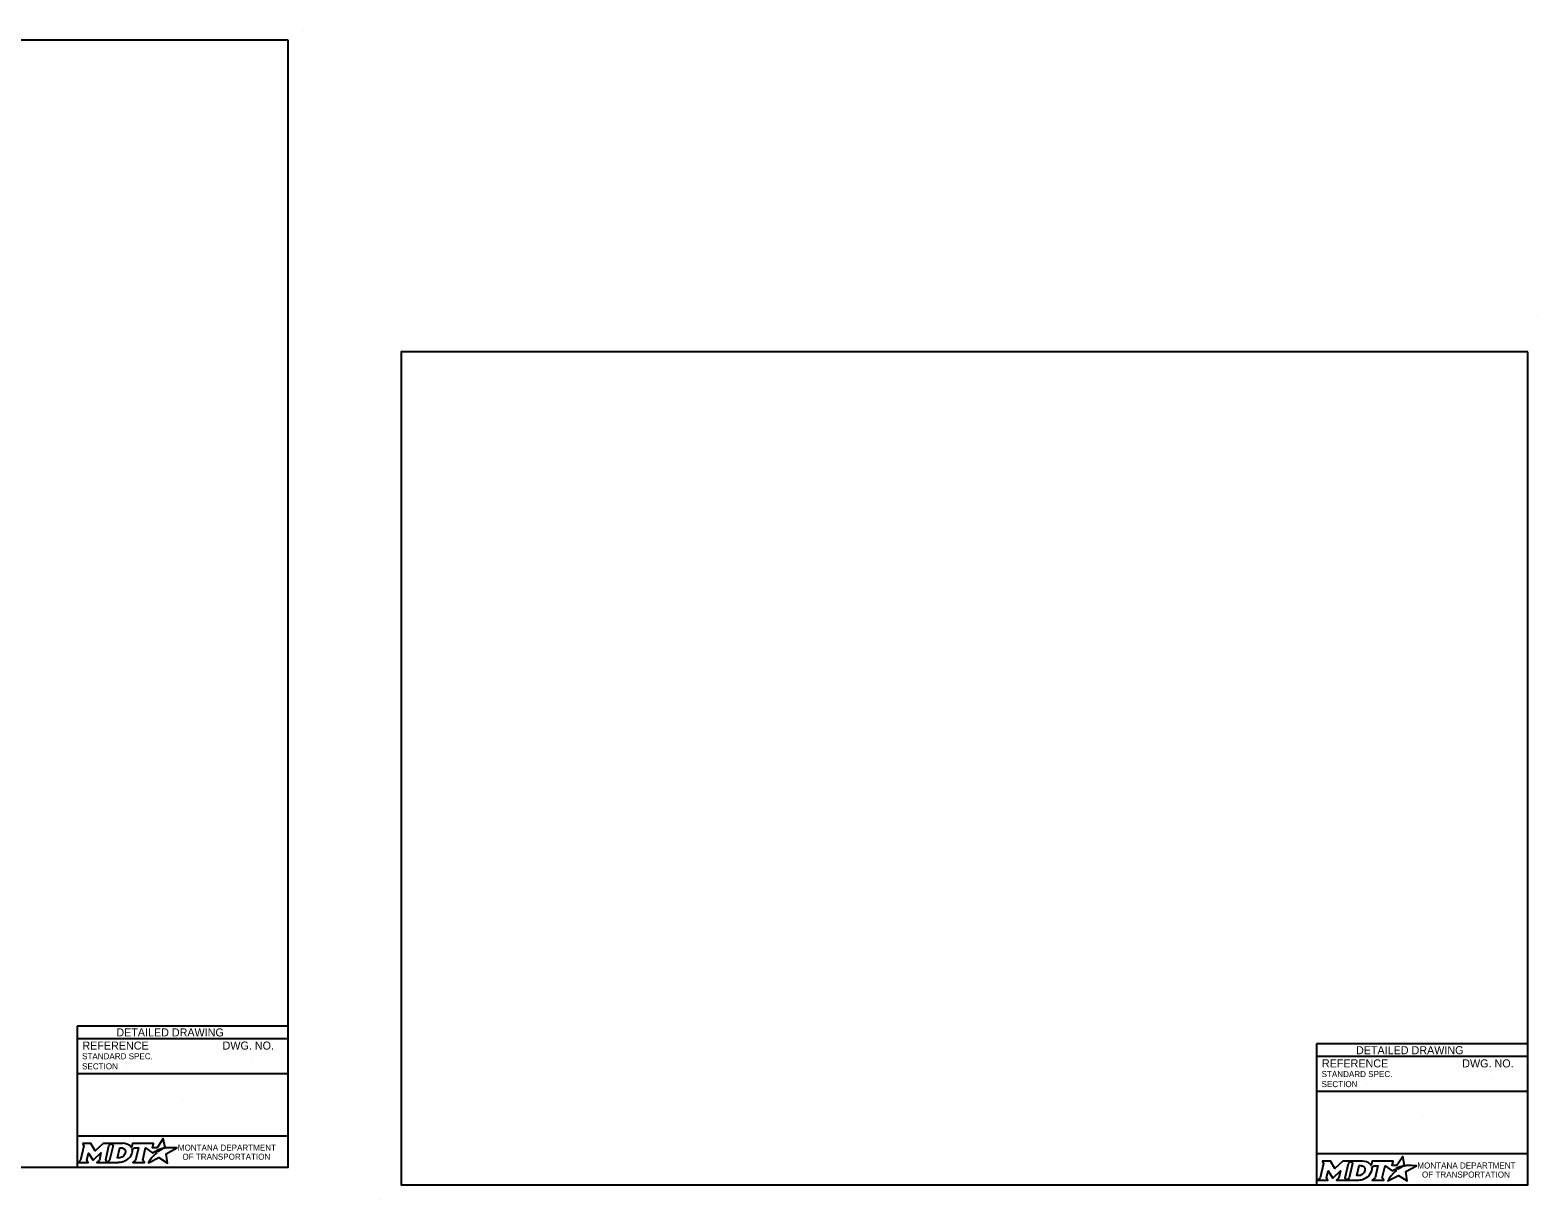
# Model space of a CAD drawing. Extents: x 49991.4 to 50021, y 49987.6 to 50011.4.
# Drawn here: x 50006.05 to 50021.04, y 49999.74 to 50011.36 of the extents above; entities that cross this region are included whole.
import ezdxf

# ---------------------------------------------------------------- set-up
doc = ezdxf.new("R2010")
doc.units = 0
for name, color, linetype in [('Default', 7, 'Continuous'), ('Level 1', 7, 'Continuous'), ('Level 2', 7, 'Continuous'), ('Level 4', 7, 'Continuous')]:
    doc.layers.add(name, color=color, linetype=linetype)

msp = doc.modelspace()

# ---------------------------------------------------------------- linework, layer by layer
at = {"layer": 'Default'}
for points in [[(50018.893, 50000.121), (50018.907, 50000.097), (50018.874, 49999.954), (50018.848, 49999.931), (50018.95, 49999.931), (50018.936, 49999.954), (50018.952, 50000.024), (50018.996, 49999.955), (50019.002, 49999.955), (50019.077, 50000.025), (50019.06, 49999.954), (50019.035, 49999.932), (50019.137, 49999.932), (50019.123, 49999.955), (50019.156, 50000.097)], [(50019.156, 50000.097), (50019.182, 50000.121), (50019.099, 50000.121), (50019.02, 50000.048), (50018.975, 50000.12), (50018.893, 50000.121)], [(50019.295, 50000.121), (50019.182, 50000.121), (50019.196, 50000.098), (50019.163, 49999.954), (50019.137, 49999.932), (50019.248, 49999.932)], [(50019.319, 50000.034), (50019.318, 50000.026), (50019.315, 50000.017), (50019.311, 50000.008), (50019.305, 50000.001), (50019.299, 49999.994), (50019.291, 49999.988), (50019.282, 49999.983), (50019.273, 49999.979), (50019.264, 49999.977), (50019.255, 49999.976), (50019.239, 49999.976), (50019.263, 50000.076), (50019.279, 50000.076), (50019.286, 50000.075), (50019.294, 50000.073), (50019.301, 50000.07), (50019.307, 50000.066), (50019.311, 50000.061), (50019.315, 50000.055), (50019.318, 50000.049), (50019.319, 50000.042), (50019.32, 50000.038), (50019.319, 50000.034)], [(50019.7, 50000.068), (50019.69, 50000.074), (50019.702, 50000.076), (50019.713, 50000.078), (50019.696, 50000.168), (50019.636, 50000.077), (50019.589, 50000.076), (50019.599, 50000.12), (50019.39, 50000.121), (50019.38, 50000.078), (50019.374, 50000.086)], [(50019.387, 50000.062), (50019.411, 50000.075), (50019.448, 50000.075), (50019.42, 49999.954), (50019.392, 49999.931), (50019.508, 49999.931), (50019.491, 49999.954), (50019.52, 50000.075), (50019.591, 50000.023), (50019.612, 50000.038), (50019.632, 50000.027)], [(50019.576, 49999.971), (50019.561, 49999.947), (50019.556, 49999.939), (50019.55, 49999.931), (50019.548, 49999.926), (50019.653, 49999.979), (50019.737, 49999.924), (50019.724, 50000.017), (50019.831, 50000.075), (50019.782, 50000.076), (50019.751, 50000.077), (50019.731, 50000.077), (50019.724, 50000.075), (50019.719, 50000.074), (50019.711, 50000.072), (50019.7, 50000.068)], [(50019.65, 50000.04), (50019.648, 50000.039), (50019.629, 50000.048), (50019.639, 50000.054), (50019.644, 50000.056), (50019.652, 50000.06), (50019.658, 50000.063), (50019.666, 50000.066), (50019.673, 50000.068), (50019.685, 50000.061), (50019.681, 50000.059), (50019.676, 50000.056), (50019.672, 50000.054), (50019.667, 50000.051), (50019.665, 50000.05), (50019.662, 50000.049), (50019.66, 50000.047), (50019.658, 50000.046), (50019.655, 50000.044), (50019.652, 50000.042), (50019.65, 50000.04)], [(50019.293, 49999.939), (50019.302, 49999.942), (50019.315, 49999.947), (50019.335, 49999.958)], [(50019.59, 49999.987), (50019.59, 49999.987)]]:
    msp.add_lwpolyline(points, dxfattribs=at)
for centre, radius, start, end in [((50019.319, 50000.042), 0.0709, 339.5329, 15.8582), ((50019.274, 50000.059), 0.118, 300.9103, 339.1383)]:
    msp.add_arc(centre, radius, start, end, dxfattribs=at)
for centre, major_axis, ratio, start_param, end_param in [((50019.293, 50000.073), (0.0834, -0.0037), 0.568097, 0.61298, 1.570796), ((50019.349, 50000.081), (0.0361, -0.0295), 0.469099, 1.225588, 1.570796), ((50019.248, 50000.08), (0, 0.148), 0.987302, 3.139398, 3.456847), ((50019.583, 49999.979), (-0.00694, -0.00806), 0.008222, 0, 3.137361), ((50019.6, 49999.997), (-0.0098, -0.0102), 0.016458, 3.141593, 6.279097), ((50019.621, 50000.017), (-0.0112, -0.0097), 0.021651, 3.157348, 6.283185)]:
    msp.add_ellipse(centre, major_axis=major_axis, ratio=ratio, start_param=start_param, end_param=end_param, dxfattribs=at)
at = {"layer": 'Level 1'}
for p, q in [((50008.765, 50011.363), (50008.765, 50011.363)), ((50021.038, 50008.524), (50021.038, 50008.524)), ((50009.537, 49999.736), (50009.537, 49999.736))]:
    msp.add_line(p, q, dxfattribs=at)
for points in [[(50008.615, 50011.263), (50000.336, 50011.263), (50000.336, 50000.062), (50008.615, 50000.062)], [(50020.938, 50008.165), (50009.737, 50008.165), (50009.737, 49999.886), (50020.938, 49999.886)]]:
    msp.add_lwpolyline(points, close=True, dxfattribs=at)
at = {"layer": 'Level 2'}
for p, q in [((50008.615, 50001.462), (50006.515, 50001.462)), ((50006.515, 50001.462), (50006.515, 50000.062)), ((50008.615, 50001.337), (50006.515, 50001.337)), ((50008.251, 50001.122), (50008.251, 50001.122)), ((50008.615, 50000.987), (50006.515, 50000.987)), ((50007.009, 50001.063), (50007.009, 50001.063)), ((50007.565, 50000.738), (50007.565, 50000.738)), ((50008.615, 50000.369), (50006.515, 50000.369))]:
    msp.add_line(p, q, dxfattribs=at)
for points in [[(50007.377, 50000.245), (50007.367, 50000.25), (50007.378, 50000.253), (50007.39, 50000.255), (50007.373, 50000.345), (50007.313, 50000.254), (50007.266, 50000.253), (50007.276, 50000.297), (50007.067, 50000.297), (50007.057, 50000.255), (50007.051, 50000.263)], [(50006.57, 50000.297), (50006.584, 50000.274), (50006.551, 50000.131), (50006.525, 50000.108), (50006.627, 50000.108), (50006.613, 50000.131), (50006.629, 50000.201), (50006.673, 50000.132), (50006.678, 50000.132), (50006.753, 50000.202), (50006.737, 50000.13), (50006.712, 50000.108), (50006.814, 50000.108), (50006.8, 50000.132), (50006.833, 50000.274)], [(50006.833, 50000.274), (50006.859, 50000.297), (50006.776, 50000.297), (50006.697, 50000.224), (50006.652, 50000.297), (50006.57, 50000.297)], [(50006.972, 50000.297), (50006.859, 50000.297), (50006.873, 50000.275), (50006.839, 50000.131), (50006.814, 50000.108), (50006.925, 50000.108)], [(50006.996, 50000.211), (50006.995, 50000.203), (50006.992, 50000.193), (50006.988, 50000.185), (50006.982, 50000.178), (50006.976, 50000.171), (50006.968, 50000.164), (50006.959, 50000.16), (50006.95, 50000.156), (50006.941, 50000.154), (50006.932, 50000.153), (50006.916, 50000.153), (50006.94, 50000.253), (50006.956, 50000.253), (50006.963, 50000.252), (50006.971, 50000.25), (50006.977, 50000.247), (50006.983, 50000.243), (50006.988, 50000.238), (50006.992, 50000.232), (50006.995, 50000.226), (50006.996, 50000.218), (50006.996, 50000.215), (50006.996, 50000.211)], [(50007.064, 50000.238), (50007.088, 50000.251), (50007.125, 50000.251), (50007.097, 50000.131), (50007.069, 50000.108), (50007.185, 50000.108), (50007.168, 50000.131), (50007.196, 50000.251), (50007.268, 50000.2), (50007.289, 50000.215), (50007.309, 50000.204)], [(50007.253, 50000.148), (50007.237, 50000.124), (50007.233, 50000.116), (50007.227, 50000.107), (50007.225, 50000.103), (50007.33, 50000.156), (50007.414, 50000.101), (50007.401, 50000.194), (50007.508, 50000.252), (50007.458, 50000.253), (50007.428, 50000.253), (50007.407, 50000.254), (50007.401, 50000.252), (50007.396, 50000.251), (50007.387, 50000.249), (50007.377, 50000.245)], [(50007.327, 50000.217), (50007.324, 50000.215), (50007.306, 50000.225), (50007.316, 50000.231), (50007.32, 50000.233), (50007.329, 50000.237), (50007.335, 50000.239), (50007.343, 50000.243), (50007.35, 50000.245), (50007.362, 50000.238), (50007.358, 50000.236), (50007.353, 50000.233), (50007.349, 50000.231), (50007.344, 50000.228), (50007.342, 50000.227), (50007.339, 50000.225), (50007.337, 50000.224), (50007.334, 50000.222), (50007.332, 50000.221), (50007.329, 50000.219), (50007.327, 50000.217)], [(50006.97, 50000.116), (50006.979, 50000.118), (50006.992, 50000.124), (50007.012, 50000.135)], [(50007.267, 50000.164), (50007.267, 50000.164)]]:
    msp.add_lwpolyline(points, dxfattribs=at)
for centre, radius, start, end in [((50006.951, 50000.236), 0.118, 300.9103, 339.1383), ((50006.995, 50000.219), 0.0709, 339.5329, 15.8582)]:
    msp.add_arc(centre, radius, start, end, dxfattribs=at)
for centre, major_axis, ratio, start_param, end_param in [((50006.97, 50000.25), (0.0834, -0.0037), 0.568097, 0.61298, 1.570796), ((50007.026, 50000.257), (0.0361, -0.0295), 0.469099, 1.225588, 1.570796), ((50007.276, 50000.174), (-0.0098, -0.0102), 0.016458, 3.141593, 6.279097), ((50007.297, 50000.194), (-0.0112, -0.0097), 0.021651, 3.157348, 6.283185), ((50006.925, 50000.257), (0, 0.148), 0.987302, 3.139398, 3.456847), ((50007.26, 50000.156), (-0.00694, -0.00806), 0.008222, 0, 3.137361)]:
    msp.add_ellipse(centre, major_axis=major_axis, ratio=ratio, start_param=start_param, end_param=end_param, dxfattribs=at)
at = {"layer": 'Level 4'}
for p, q in [((50020.938, 50001.286), (50018.838, 50001.286)), ((50018.838, 50001.286), (50018.838, 49999.886)), ((50020.938, 50001.161), (50018.838, 50001.161)), ((50020.574, 50000.946), (50020.574, 50000.946)), ((50020.938, 50000.811), (50018.838, 50000.811)), ((50019.332, 50000.886), (50019.332, 50000.886)), ((50019.888, 50000.562), (50019.888, 50000.562)), ((50020.938, 50000.193), (50018.838, 50000.193))]:
    msp.add_line(p, q, dxfattribs=at)

# ---------------------------------------------------------------- texts
at = {"layer": 'Default'}
for s, p in [('MONTANA DEPARTMENT', (50019.84, 50000.047)), ('OF TRANSPORTATION', (50019.886, 49999.957))]:
    msp.add_text(s, height=0.06, rotation=360, dxfattribs=at).set_placement(p)
at = {"layer": 'Level 2'}
for s, height, p in [('DETAILED DRAWING', 0.0799, (50006.906, 50001.36)), ('REFERENCE', 0.08, (50006.568, 50001.229)), ('DWG. NO.', 0.08, (50007.962, 50001.229)), ('STANDARD SPEC.', 0.06, (50006.565, 50001.133)), ('SECTION', 0.06, (50006.565, 50001.033))]:
    msp.add_text(s, height=height, dxfattribs=at).set_placement(p)
for s, p in [('MONTANA DEPARTMENT', (50007.517, 50000.224)), ('OF TRANSPORTATION', (50007.563, 50000.134))]:
    msp.add_text(s, height=0.06, rotation=360, dxfattribs=at).set_placement(p)
at = {"layer": 'Level 4'}
for s, height, p in [('DETAILED DRAWING', 0.0799, (50019.23, 50001.183)), ('REFERENCE', 0.08, (50018.891, 50001.052)), ('DWG. NO.', 0.08, (50020.286, 50001.052)), ('STANDARD SPEC.', 0.06, (50018.888, 50000.956)), ('SECTION', 0.06, (50018.888, 50000.856))]:
    msp.add_text(s, height=height, dxfattribs=at).set_placement(p)

doc.saveas('drawing.dxf')
